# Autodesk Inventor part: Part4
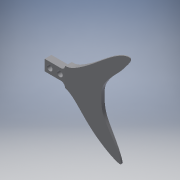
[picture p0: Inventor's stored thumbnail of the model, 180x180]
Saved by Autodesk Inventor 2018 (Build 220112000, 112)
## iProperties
Created: 2019-06
Part Number: Part4
Material: Generic
Document SubType Name: Modeling
Designer: multivac
Density: 1 g/cm^3
Appearance: Default
Author: multivac
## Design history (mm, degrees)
sketch "Sketch1"
  geometry: L1 (-255.123, 76.009)-(52.17, 76.009); L2 (52.17, 76.009)-(52.17, -88.577); L3 (52.17, -88.577)-(-255.123, -88.577); L4 (-255.123, -88.577)-(-255.123, 76.009); L5 (0.907, 7.657)-(3.625, 7.657); L6 (3.625, 7.657)-(6.823, 8.776); L7 (6.823, 8.776)-(15.937, 14.373); L8 (15.937, 14.373)-(26.17, 23.167); L9 (26.17, 23.167)-(36.883, 31.561); L10 (36.883, 31.561)-(43.519, 34.519); L11 (43.519, 34.519)-(46.956, 34.999); L12 (46.956, 34.999)-(47.756, 32.6); L13 (47.756, 32.6)-(42.399, 26.285); L14 (42.399, 26.285)-(39.521, 21.888); L15 (39.521, 21.888)-(32.886, 15.972); L16 (32.886, 15.972)-(26.97, 7.657); L17 (26.97, 7.657)-(26.25, 3.58); L18 (26.25, 3.58)-(26.25, -6.973); L19 (26.25, -6.973)-(28.249, -13.529); L20 (28.249, -13.529)-(35.524, -24.162); L21 (35.524, -24.162)-(40.561, -34.475); L22 (40.561, -34.475)-(40.561, -37.033); L23 (40.561, -37.033)-(39.042, -37.033); L24 (39.042, -37.033)-(32.006, -33.995); L25 (32.006, -33.995)-(22.253, -26.8); L26 (22.253, -26.8)-(15.217, -19.925); L27 (15.217, -19.925)-(8.662, -11.85); L28 (8.662, -11.85)-(4.585, -7.853); L29 (4.585, -7.853)-(0.907, -6.284); L30 (0.907, 7.657)-(0.907, -6.284); 1 further point; 1 other entity
  constraints: 3 vertical, 2 end point, 2 horizontal, 5 other
extrude "Extrusion1" new body sketch "Sketch1" distance "d16" = 5; taper "d17" = 0 deg
sketch "Sketch2"
  geometry: L1 (-0.907, 0)-(-0.907, 5) reference; L2 (-0.907, 5)-(-48.8, 2.5); L3 (-48.8, 2.5)-(-0.907, 0); 1 further point
  constraints: 4 end point
extrude "Extrusion2" sketch "Sketch2" stored distance "d27" = 80; taper "d28" = 0 deg
sketch "Sketch3"
  geometry: L1 (5, 6.971)-(5, 10.971); L2 (5, 10.971)-(0, 10.971); L3 (0, 10.971)-(0, 2.971); L4 (0, 10.971)-(8, 10.971); L5 (0, 2.971)-(5, 2.971); L6 (5, 2.971)-(5, 6.971)
  constraints: 12 end point, 2 perpendicular, 1 horizontal, 1 vertical
  dimensions: "d29" = 4 distance of L1.start L1.end; "d30" = 8 distance of L2.end L3.end; "d31" = 90 deg angle of L3 L4 (derived)
extrude "Extrusion3" join sketch "Sketch3" distance "d32" = 15; taper "d33" = 0 deg
fillet "Fillet1" dims "d34" = 3
sketch "Sketch4"
  geometry: L1 (0, 0)-(0, 8) reference; L2 (0, 4)-(3.75, 4); C1 r 2 at (-3.75, 4); C2 r 2 at (-11.25, 4)
  constraints: 2 centre point, 2 end point, 1 horizontal, 1 midpoint
  dimensions: "d38" = 4 diameter of C1; "d39" = 4 diameter of C2
extrude "Extrusion4" cut sketch "Sketch4" distance "d40" = 15; taper "d41" = 0 deg
body "Solid1"
node "Image1"
